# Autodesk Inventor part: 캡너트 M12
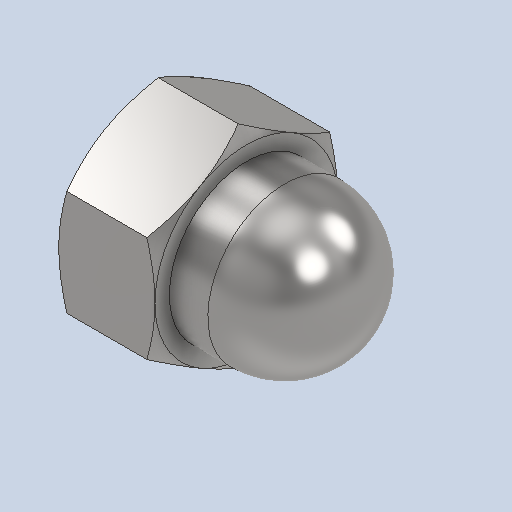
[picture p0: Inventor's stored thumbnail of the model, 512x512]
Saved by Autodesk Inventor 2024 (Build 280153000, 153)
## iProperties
Created: 2024-07
Part Number: 캡너트 M12
Material: 강철, 연강
Description: 6각 둥근캡 너트
Document SubType Name: Modeling
Designer: com
Density: 7.85 g/cm^3
Appearance: 기본값
Author: jhkim
Sending System: Autodesk Inventor 2025
Preprocessor: ST-DEVELOPER v20
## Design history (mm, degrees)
feature "Solid1"
node "솔리드1"
